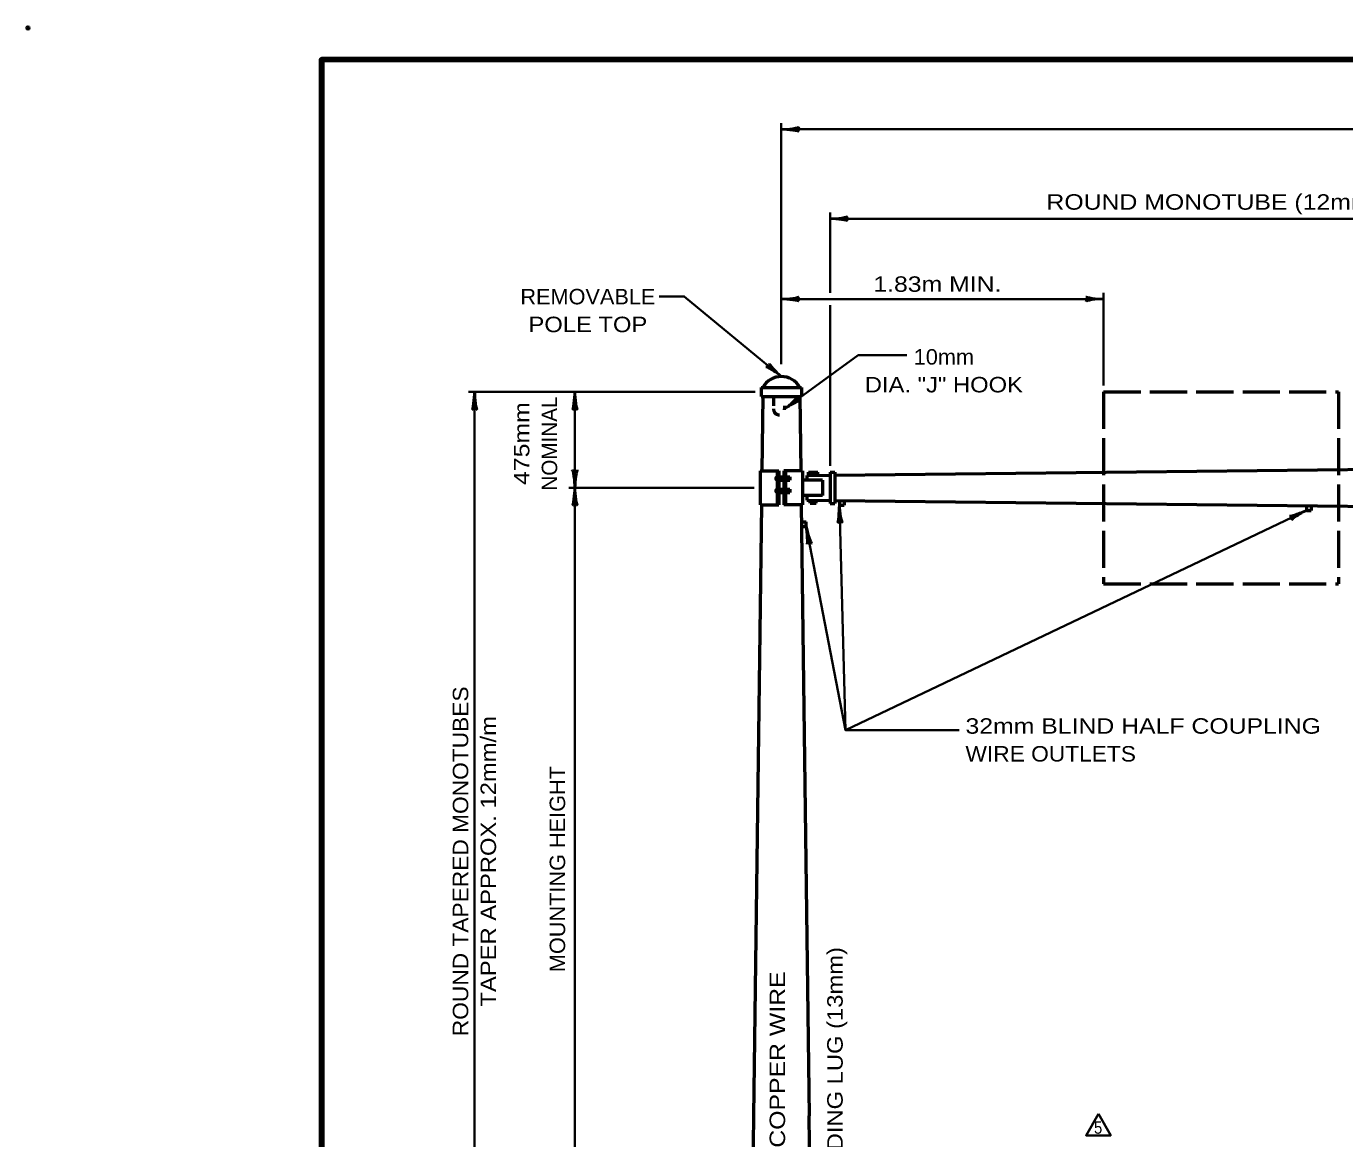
# Model space of a CAD drawing. Extents: x -46 to 809, y -15 to 529.
# Drawn here: x -46.4 to 209.6, y 313 to 529 of the extents above; entities that cross this region are included whole.
import ezdxf
from ezdxf.enums import TextEntityAlignment as Align

# ---------------------------------------------------------------- set-up
doc = ezdxf.new("R2010")
doc.units = 0
doc.header["$LTSCALE"] = 1.2
doc.header["$PDMODE"] = 32
doc.header["$PDSIZE"] = 0.6
doc.linetypes.add('LONG_DASHED', pattern=[7.5, 6, -1.5])
doc.linetypes.add('SHORT_DASHED', pattern=[2.7, 1.5, -1.2])
doc.layers.add('1', color=7, linetype='Continuous', lineweight=35)

msp = doc.modelspace()

# ---------------------------------------------------------------- linework, layer by layer
at = {"layer": '1'}
for p, q in [((100.214, 463.363), (100.214, 510.163)), ((100.214, 508.963), (467.782, 508.963)), ((109.698, 477.203), (109.698, 492.814)), ((109.698, 491.614), (283.998, 491.614)), ((162.798, 459.203), (162.798, 477.203)), ((162.798, 476.003), (100.214, 476.003)), ((109.698, 443.614), (109.698, 474.803)), ((95.114, 457.963), (39.461, 457.963)), ((60.13, 439.364), (60.13, 457.963)), ((94.93, 439.364), (58.93, 439.364)), ((60.13, 439.364), (60.13, 266.073)), ((112.67, 392.32), (202.206, 434.963)), ((112.67, 392.32), (134.761, 392.32))]:
    msp.add_line(p, q, dxfattribs=at)
at = {"layer": '1', "lineweight": 53}
for p, q in [((96.314, 458.863), (104.114, 458.863)), ((96.314, 458.863), (96.314, 457.063)), ((104.114, 458.863), (104.114, 457.063)), ((96.314, 457.063), (104.114, 457.063)), ((96.614, 457.063), (96.43, 442.664)), ((103.814, 457.063), (103.998, 442.664)), ((110.598, 441.824), (280.998, 443.714)), ((96.13, 442.664), (99.73, 442.664)), ((96.13, 442.664), (96.13, 436.064)), ((99.43, 442.664), (99.43, 436.064)), ((99.73, 442.664), (99.73, 436.064)), ((99.73, 441.464), (100.698, 441.464)), ((99.73, 440.864), (100.698, 440.864)), ((104.298, 442.664), (100.698, 442.664)), ((100.698, 442.664), (100.698, 436.064)), ((100.998, 442.664), (100.998, 436.064)), ((100.998, 441.764), (101.298, 441.764)), ((100.998, 440.564), (101.298, 440.564)), ((101.298, 441.764), (101.298, 440.564)), ((101.298, 441.464), (101.898, 441.464)), ((101.298, 440.864), (101.898, 440.864)), ((101.898, 441.464), (101.898, 440.864)), ((104.298, 442.664), (104.298, 436.064)), ((108.198, 440.864), (104.298, 440.864)), ((105.198, 441.764), (109.698, 441.814)), ((105.198, 441.764), (105.198, 440.864)), ((105.498, 441.768), (105.498, 442.368)), ((105.498, 442.368), (107.298, 442.368)), ((107.298, 441.768), (107.298, 442.368)), ((108.198, 440.864), (108.198, 437.864)), ((109.698, 442.414), (109.698, 436.314)), ((109.698, 442.414), (110.598, 442.414)), ((110.598, 442.414), (110.598, 436.314)), ((99.73, 439.064), (100.698, 439.064)), ((99.73, 438.464), (100.698, 438.464)), ((100.998, 439.364), (101.298, 439.364)), ((100.998, 438.164), (101.298, 438.164)), ((101.298, 439.364), (101.298, 438.164)), ((101.298, 439.064), (101.898, 439.064)), ((101.298, 438.464), (101.898, 438.464)), ((101.898, 439.064), (101.898, 438.464)), ((108.198, 437.864), (104.298, 437.864)), ((105.198, 437.864), (105.198, 436.964)), ((96.346, 436.064), (94.829, 317.409)), ((96.13, 436.064), (99.73, 436.064)), ((104.298, 436.064), (100.698, 436.064)), ((104.082, 436.064), (105.599, 317.406)), ((105.198, 436.964), (109.698, 436.914)), ((105.798, 436.358), (105.798, 436.958)), ((105.798, 436.358), (106.998, 436.344)), ((106.998, 436.344), (106.998, 436.944)), ((109.698, 436.314), (110.598, 436.314)), ((110.598, 436.904), (280.998, 435.014)), ((111.498, 436.894), (111.498, 435.994)), ((111.498, 435.994), (112.398, 435.994)), ((112.398, 436.894), (112.398, 435.994)), ((203.106, 435.863), (203.106, 434.963)), ((104.125, 432.764), (105.025, 432.764)), ((105.025, 431.864), (105.025, 432.764)), ((104.125, 431.864), (105.025, 431.864)), ((94.829, 317.409), (94.181, 271.521)), ((105.533, 317.409), (106.181, 271.521))]:
    msp.add_line(p, q, dxfattribs=at)
at = {"layer": '1', "linetype": 'SHORT_DASHED', "lineweight": 53}
for p, q in [((98.714, 457.063), (98.714, 454.663)), ((100.814, 455.263), (100.814, 454.663))]:
    msp.add_line(p, q, dxfattribs=at)
at = {"layer": '1', "linetype": 'LONG_DASHED', "lineweight": 53}
for p, q in [((162.798, 458.003), (162.798, 420.725)), ((162.798, 458.003), (208.398, 458.003)), ((208.398, 458.003), (208.398, 420.725)), ((162.798, 420.725), (208.398, 420.725))]:
    msp.add_line(p, q, dxfattribs=at)
at = {"layer": '1', "lineweight": 158}
msp.add_lwpolyline([(802.618, 522.556), (10.918, 522.456), (11.018, -3.544)], dxfattribs=at)
at = {"layer": '1'}
for points in [[(100.214, 460.963), (81.368, 476.53), (76.526, 476.53)], [(100.814, 454.663), (115.159, 465.141), (124.597, 465.141)], [(40.661, 139.065), (40.661, 266.073), (40.661, 457.963)], [(105.025, 431.864), (112.67, 392.32), (111.498, 435.994)]]:
    msp.add_lwpolyline(points, dxfattribs=at)
at = {"layer": '1', "lineweight": 53}
msp.add_lwpolyline([(202.206, 435.863), (202.206, 434.963), (203.106, 434.963)], dxfattribs=at)
at = {"layer": '1'}
msp.add_lwpolyline([(161.777, 317.769), (159.377, 313.612), (164.177, 313.612)], close=True, dxfattribs=at)
at = {"layer": '1', "lineweight": 53}
for centre, radius, start, end in [((100.214, 456.866), 4.097, 29.1749, 150.8251), ((99.473, 441.164), 0.303, 98.06402, 261.93598), ((99.473, 438.764), 0.303, 98.06402, 261.93598)]:
    msp.add_arc(centre, radius, start, end, dxfattribs=at)
at = {"layer": '1', "linetype": 'SHORT_DASHED', "lineweight": 53}
msp.add_arc((99.764, 454.596), 1.052, 176.35082, 3.64918, dxfattribs=at)
at = {"layer": '1', "lineweight": 40}
for centre, major_axis, ratio, start_param, end_param in [((101.524, 509.294), (-2.143, -0.187), 0.122415, 0.8963533, 3.1415927), ((101.559, 508.709), (-2.108, 0.211), 0.07063, 3.1407148, 5.41811), ((111.043, 491.36), (-2.108, 0.211), 0.07063, 3.1407148, 5.41811), ((111.008, 491.946), (-2.143, -0.187), 0.122415, 0.8963533, 3.1415927), ((101.524, 476.335), (-2.143, -0.187), 0.122415, 0.8963533, 3.1415927), ((101.524, 476.335), (-2.143, -0.187), 0.122415, 0.8963533, 3.1415927), ((161.454, 476.257), (2.108, -0.211), 0.07063, 3.1407148, 5.41811), ((101.559, 475.749), (-2.108, 0.211), 0.07063, 3.1407148, 5.41811), ((101.559, 475.749), (-2.108, 0.211), 0.07063, 3.1407148, 5.41811), ((161.489, 475.672), (2.143, 0.187), 0.122415, 0.8963533, 3.1415927), ((99.339, 462.015), (1.491, -1.505), 0.07063, 3.1407148, 5.41811), ((98.993, 461.541), (1.771, -1.22), 0.122415, 0.8963533, 3.1415927), ((40.407, 456.618), (0.211, 2.108), 0.07063, 3.1407148, 5.41811), ((40.993, 456.654), (-0.187, 2.143), 0.122415, 0.8963533, 3.1415927), ((59.876, 456.618), (0.211, 2.108), 0.07063, 3.1407148, 5.41811), ((59.876, 456.618), (0.211, 2.108), 0.07063, 3.1407148, 5.41811), ((60.462, 456.654), (-0.187, 2.143), 0.122415, 0.8963533, 3.1415927), ((60.462, 456.654), (-0.187, 2.143), 0.122415, 0.8963533, 3.1415927), ((101.676, 455.703), (-1.62, -1.415), 0.122415, 0.8963533, 3.1415927), ((102.05, 455.251), (1.826, 1.073), 0.07063, 6.2823074, 8.5597026), ((59.798, 440.674), (0.187, -2.143), 0.122415, 0.8963533, 3.1415927), ((59.798, 440.674), (0.187, -2.143), 0.122415, 0.8963533, 3.1415927), ((60.384, 440.709), (-0.211, -2.108), 0.07063, 3.1407148, 5.41811), ((60.384, 440.709), (-0.211, -2.108), 0.07063, 3.1407148, 5.41811), ((59.876, 438.02), (0.211, 2.108), 0.07063, 3.1407148, 5.41811), ((59.876, 438.02), (0.211, 2.108), 0.07063, 3.1407148, 5.41811), ((60.462, 438.055), (-0.187, 2.143), 0.122415, 0.8963533, 3.1415927), ((60.462, 438.055), (-0.187, 2.143), 0.122415, 0.8963533, 3.1415927), ((111.28, 434.643), (-0.154, -2.113), 0.07063, 6.2823074, 8.5597026), ((111.865, 434.694), (-0.245, 2.137), 0.122415, 0.8963533, 3.1415927), ((200.883, 434.614), (1.994, 0.716), 0.07063, 3.1407148, 5.41811), ((201.166, 434.101), (1.854, 1.091), 0.122415, 0.8963533, 3.1415927), ((105.031, 430.496), (-0.193, 2.109), 0.07063, 3.1407148, 5.41811), ((105.031, 430.496), (-0.193, 2.109), 0.07063, 3.1407148, 5.41811), ((105.599, 430.642), (-0.591, 2.068), 0.122415, 0.8963533, 3.1415927), ((105.599, 430.642), (-0.591, 2.068), 0.122415, 0.8963533, 3.1415927)]:
    msp.add_ellipse(centre, major_axis=major_axis, ratio=ratio, start_param=start_param, end_param=end_param, dxfattribs=at)
at = {"layer": '1'}
msp.add_point((-46.082, 528.656), dxfattribs=at)

# ---------------------------------------------------------------- texts
for s, height, width, p in [('ROUND MONOTUBE (12mm/m TAPER)', 3, 1.2, (195.428, 493.356)), ('1.83m MIN.', 3, 1.2, (130.519, 477.413)), ('REMOVABLE', 3, 1.05, (62.654, 474.981)), ('POLE TOP', 3, 1.15, (62.654, 469.581)), ('10mm', 3, 1.05, (131.778, 463.284)), ('DIA. "J" HOOK', 3, 1.15, (131.778, 457.884)), ('5', 2.4, 0.9, (161.728, 313.933))]:
    msp.add_text(s, height=height, dxfattribs=dict(at, width=width)).set_placement(p, align=Align.CENTER)
for s, width, p in [('475mm', 1.2, (51.285, 447.943)), ('ROUND TAPERED MONOTUBES', 1.1, (39.418, 366.828)), ('TAPER APPROX. 12mm/m', 1.15, (44.818, 366.828)), ('MOUNTING HEIGHT', 1.05, (58.233, 365.317)), ('GROUNDING LUG (13mm)', 1.15, (112.132, 321.857)), (' 4 AWG COPPER WIRE', 1.2, (100.945, 319.241))]:
    msp.add_text(s, height=3, rotation=90, dxfattribs=dict(at, width=width)).set_placement(p, align=Align.CENTER)
msp.add_text('NOMINAL', height=3, rotation=90, dxfattribs=at).set_placement((56.685, 447.943), align=Align.CENTER)
for s, width, p in [('32mm BLIND HALF COUPLING', 1.2, (135.976, 391.606)), ('WIRE OUTLETS', 1.1, (135.976, 386.206))]:
    msp.add_text(s, height=3, dxfattribs=dict(at, width=width)).set_placement(p)

doc.saveas('drawing.dxf')
